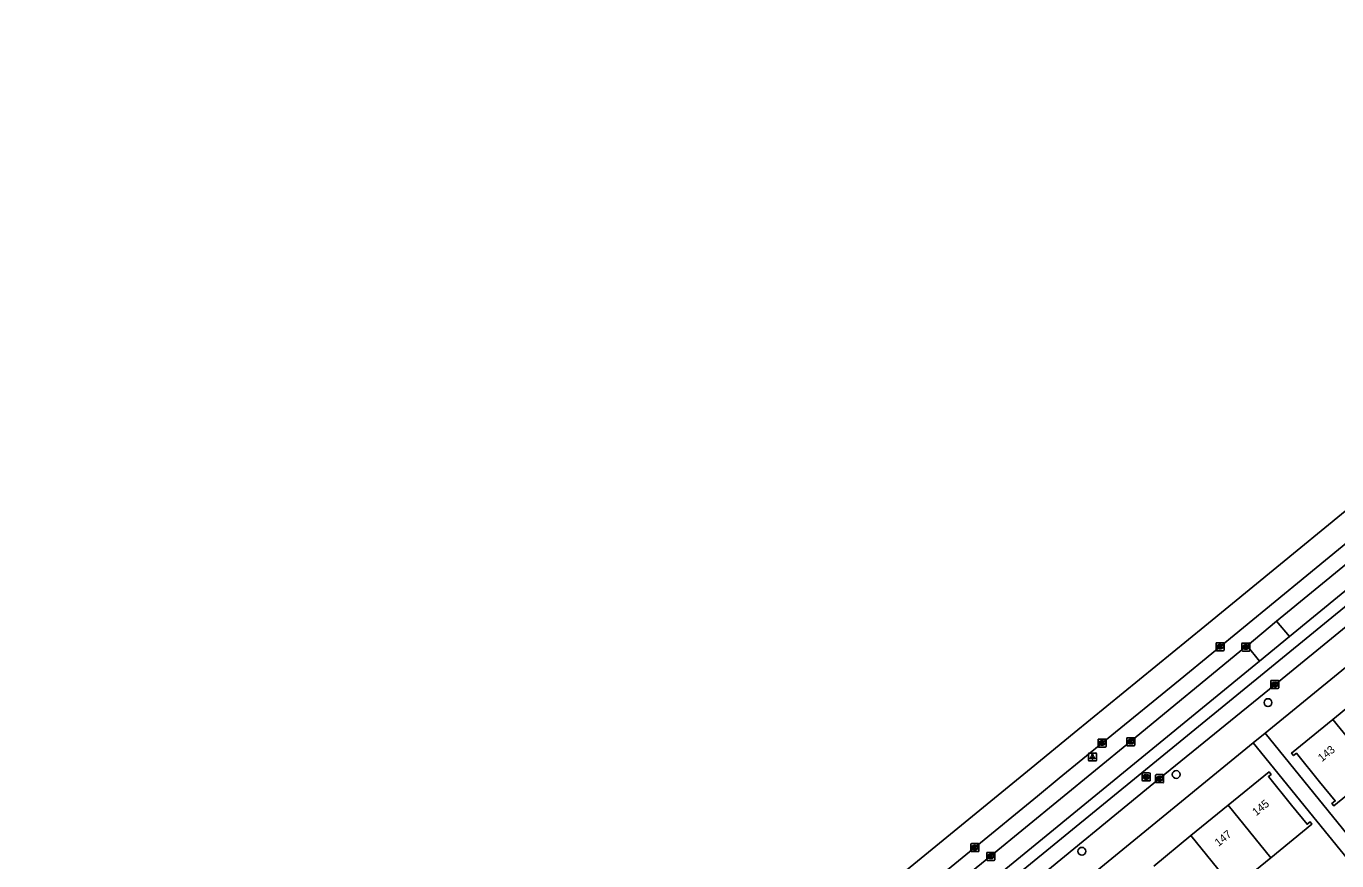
# Model space of a CAD drawing. Extents: x 162532 to 163264, y 381233 to 382042.
# Drawn here: x 162536.5 to 162700.3, y 381924.3 to 382028.5 of the extents above; entities that cross this region are included whole.
import ezdxf

# ---------------------------------------------------------------- set-up
doc = ezdxf.new("R2010")
doc.units = 0
for name, color, linetype in [('IMGEO_Boom', 7, 'Continuous'), ('IMGEO_Kolk', 7, 'Continuous'), ('IMGEO_Lichtpunt', 7, 'Continuous'), ('IMGEO_Pand', 7, 'Continuous'), ('IMGEO_Pand_nummerreeks', 7, 'Continuous'), ('IMGEO_Rijbaan_lokaal_gesloten', 7, 'Continuous'), ('IMGEO_Rijbaan_lokaal_open', 7, 'Continuous'), ('IMGEO_Rijbaan_regionaal_gesloten', 7, 'Continuous'), ('IMGEO_Rioolput', 7, 'Continuous'), ('IMGEO_Voetpad_open', 7, 'Continuous')]:
    doc.layers.add(name, color=color, linetype=linetype)

msp = doc.modelspace()

# ---------------------------------------------------------------- linework, layer by layer
at = {"layer": 'IMGEO_Boom'}
for centre in [(162691.72, 381944.05), (162680.25, 381935.07), (162668.46, 381925.48)]:
    msp.add_circle(centre, 0.489, dxfattribs=at)
at = {"layer": 'IMGEO_Kolk'}
for p, q in [((162685.23, 381950.6), (162685.23, 381951.45)), ((162685.3, 381951.53), (162686.16, 381951.53)), ((162685.72, 381951.31), (162685.74, 381951.31)), ((162685.74, 381950.75), (162685.72, 381950.75)), ((162686.23, 381951.45), (162686.23, 381950.6)), ((162688.46, 381950.57), (162688.46, 381951.42)), ((162688.53, 381951.49), (162689.38, 381951.49)), ((162688.94, 381951.27), (162688.97, 381951.27)), ((162688.97, 381950.71), (162688.94, 381950.71)), ((162689.46, 381951.42), (162689.46, 381950.57)), ((162686.16, 381950.53), (162685.3, 381950.53)), ((162689.38, 381950.49), (162688.53, 381950.49)), ((162692.07, 381945.89), (162692.07, 381946.74)), ((162692.15, 381946.81), (162693, 381946.81)), ((162693, 381945.81), (162692.15, 381945.81)), ((162692.56, 381946.59), (162692.59, 381946.59)), ((162692.58, 381946.03), (162692.56, 381946.03)), ((162693.07, 381946.74), (162693.07, 381945.89)), ((162670.48, 381938.57), (162670.48, 381939.42)), ((162670.56, 381939.5), (162671.41, 381939.5)), ((162670.97, 381939.28), (162671, 381939.28)), ((162671.48, 381939.42), (162671.48, 381938.57)), ((162674.08, 381938.73), (162674.08, 381939.59)), ((162674.15, 381939.66), (162675, 381939.66)), ((162674.56, 381939.44), (162674.59, 381939.44)), ((162675.08, 381939.59), (162675.08, 381938.73)), ((162671.41, 381938.5), (162670.56, 381938.5)), ((162670.99, 381938.72), (162670.97, 381938.72)), ((162675, 381938.66), (162674.15, 381938.66)), ((162674.59, 381938.88), (162674.56, 381938.88)), ((162677.67, 381934.12), (162677.67, 381934.97)), ((162677.74, 381935.05), (162678.6, 381935.05)), ((162678.18, 381934.27), (162678.15, 381934.27)), ((162678.16, 381934.83), (162678.18, 381934.83)), ((162678.67, 381934.97), (162678.67, 381934.12)), ((162678.6, 381934.05), (162677.74, 381934.05)), ((162654.58, 381925.52), (162654.58, 381926.38)), ((162654.66, 381926.45), (162655.51, 381926.45)), ((162655.07, 381926.23), (162655.1, 381926.23)), ((162655.58, 381926.38), (162655.58, 381925.52)), ((162655.51, 381925.45), (162654.66, 381925.45)), ((162655.09, 381925.67), (162655.07, 381925.67)), ((162656.57, 381924.41), (162656.57, 381925.26)), ((162656.64, 381925.34), (162657.49, 381925.34)), ((162657.05, 381925.12), (162657.08, 381925.12)), ((162657.08, 381924.56), (162657.05, 381924.56)), ((162657.57, 381925.26), (162657.57, 381924.41)), ((162657.49, 381924.34), (162656.64, 381924.34))]:
    msp.add_line(p, q, dxfattribs=at)
for points in [[(162685.23, 381950.6), (162685.23, 381951.45)], [(162685.3, 381951.53), (162686.16, 381951.53)], [(162685.55, 381951.23), (162685.67, 381951.23), (162685.67, 381951.08), (162685.8, 381951.23), (162685.97, 381951.23), (162685.82, 381951.08), (162685.97, 381950.83), (162685.82, 381950.83), (162685.74, 381950.99), (162685.67, 381950.93), (162685.67, 381950.83), (162685.55, 381950.83), (162685.55, 381951.23)], [(162686.23, 381951.45), (162686.23, 381950.6)], [(162688.46, 381950.57), (162688.46, 381951.42)], [(162688.53, 381951.49), (162689.38, 381951.49)], [(162688.78, 381951.19), (162688.9, 381951.19), (162688.9, 381951.04), (162689.03, 381951.19), (162689.19, 381951.19), (162689.05, 381951.04), (162689.2, 381950.79), (162689.05, 381950.79), (162688.96, 381950.96), (162688.9, 381950.89), (162688.9, 381950.79), (162688.78, 381950.79), (162688.78, 381951.19)], [(162689.46, 381951.42), (162689.46, 381950.57)], [(162686.16, 381950.53), (162685.3, 381950.53)], [(162689.38, 381950.49), (162688.53, 381950.49)], [(162692.07, 381945.89), (162692.07, 381946.74)], [(162692.15, 381946.81), (162693, 381946.81)], [(162693, 381945.81), (162692.15, 381945.81)], [(162692.39, 381946.51), (162692.52, 381946.51), (162692.52, 381946.36), (162692.65, 381946.51), (162692.81, 381946.51), (162692.67, 381946.36), (162692.82, 381946.11), (162692.67, 381946.11), (162692.58, 381946.28), (162692.52, 381946.21), (162692.52, 381946.11), (162692.39, 381946.11), (162692.39, 381946.51)], [(162693.07, 381946.74), (162693.07, 381945.89)], [(162670.48, 381938.57), (162670.48, 381939.42)], [(162670.56, 381939.5), (162671.41, 381939.5)], [(162670.8, 381939.2), (162670.93, 381939.2), (162670.93, 381939.04), (162671.06, 381939.2), (162671.22, 381939.2), (162671.07, 381939.05), (162671.23, 381938.8), (162671.07, 381938.8), (162670.99, 381938.96), (162670.93, 381938.89), (162670.93, 381938.8), (162670.8, 381938.8), (162670.8, 381939.2)], [(162671.48, 381939.42), (162671.48, 381938.57)], [(162674.08, 381938.73), (162674.08, 381939.59)], [(162674.15, 381939.66), (162675, 381939.66)], [(162674.4, 381939.36), (162674.52, 381939.36), (162674.52, 381939.21), (162674.65, 381939.36), (162674.81, 381939.36), (162674.67, 381939.21), (162674.82, 381938.96), (162674.67, 381938.96), (162674.58, 381939.12), (162674.52, 381939.06), (162674.52, 381938.96), (162674.4, 381938.96), (162674.4, 381939.36)], [(162675.08, 381939.59), (162675.08, 381938.73)], [(162671.41, 381938.5), (162670.56, 381938.5)], [(162675, 381938.66), (162674.15, 381938.66)], [(162677.67, 381934.12), (162677.67, 381934.97)], [(162677.74, 381935.05), (162678.6, 381935.05)], [(162677.99, 381934.75), (162678.11, 381934.75), (162678.11, 381934.6), (162678.24, 381934.75), (162678.41, 381934.75), (162678.26, 381934.6), (162678.41, 381934.35), (162678.26, 381934.35), (162678.18, 381934.51), (162678.11, 381934.45), (162678.11, 381934.35), (162677.99, 381934.35), (162677.99, 381934.75)], [(162678.67, 381934.97), (162678.67, 381934.12)], [(162678.6, 381934.05), (162677.74, 381934.05)], [(162654.58, 381925.52), (162654.58, 381926.38)], [(162654.66, 381926.45), (162655.51, 381926.45)], [(162654.9, 381926.15), (162655.03, 381926.15), (162655.03, 381926), (162655.16, 381926.15), (162655.32, 381926.15), (162655.17, 381926), (162655.33, 381925.75), (162655.17, 381925.75), (162655.09, 381925.91), (162655.03, 381925.85), (162655.03, 381925.75), (162654.9, 381925.75), (162654.9, 381926.15)], [(162655.58, 381926.38), (162655.58, 381925.52)], [(162655.51, 381925.45), (162654.66, 381925.45)], [(162656.57, 381924.41), (162656.57, 381925.26)], [(162656.64, 381925.34), (162657.49, 381925.34)], [(162656.89, 381925.04), (162657.01, 381925.04), (162657.01, 381924.89), (162657.14, 381925.04), (162657.3, 381925.04), (162657.16, 381924.89), (162657.31, 381924.64), (162657.16, 381924.64), (162657.07, 381924.8), (162657.01, 381924.73), (162657.01, 381924.64), (162656.89, 381924.64), (162656.89, 381925.04)], [(162657.57, 381925.26), (162657.57, 381924.41)], [(162657.49, 381924.34), (162656.64, 381924.34)]]:
    msp.add_lwpolyline(points, dxfattribs=at)
for centre, start, end in [((162685.31, 381951.45), 91.552, 178.448), ((162685.31, 381951.45), 91.552, 178.448), ((162686.15, 381951.45), 1.552, 88.448), ((162686.15, 381951.45), 1.552, 88.448), ((162688.53, 381951.42), 91.552, 178.448), ((162688.53, 381951.42), 91.552, 178.448), ((162689.38, 381951.42), 1.552, 88.448), ((162689.38, 381951.42), 1.552, 88.448), ((162685.31, 381950.6), 181.552, 268.448), ((162685.31, 381950.6), 181.552, 268.448), ((162686.15, 381950.6), 271.552, 358.448), ((162686.15, 381950.6), 271.552, 358.448), ((162688.53, 381950.57), 181.552, 268.448), ((162688.53, 381950.57), 181.552, 268.448), ((162689.38, 381950.57), 271.552, 358.448), ((162689.38, 381950.57), 271.552, 358.448), ((162692.15, 381946.74), 91.552, 178.448), ((162692.15, 381946.74), 91.552, 178.448), ((162692.15, 381945.89), 181.552, 268.448), ((162692.15, 381945.89), 181.552, 268.448), ((162693, 381946.74), 1.552, 88.448), ((162693, 381946.74), 1.552, 88.448), ((162693, 381945.89), 271.552, 358.448), ((162693, 381945.89), 271.552, 358.448), ((162670.56, 381939.42), 91.552, 178.448), ((162670.56, 381939.42), 91.552, 178.448), ((162671.41, 381939.42), 1.552, 88.448), ((162671.41, 381939.42), 1.552, 88.448), ((162674.15, 381939.58), 91.552, 178.448), ((162674.15, 381939.58), 91.552, 178.448), ((162675, 381939.58), 1.552, 88.448), ((162675, 381939.58), 1.552, 88.448), ((162670.56, 381938.57), 181.552, 268.448), ((162670.56, 381938.57), 181.552, 268.448), ((162671.41, 381938.57), 271.552, 358.448), ((162671.41, 381938.57), 271.552, 358.448), ((162674.15, 381938.74), 181.552, 268.448), ((162674.15, 381938.74), 181.552, 268.448), ((162675, 381938.74), 271.552, 358.448), ((162675, 381938.74), 271.552, 358.448), ((162677.74, 381934.97), 91.552, 178.448), ((162677.74, 381934.97), 91.552, 178.448), ((162678.59, 381934.97), 1.552, 88.448), ((162678.59, 381934.97), 1.552, 88.448), ((162677.74, 381934.12), 181.552, 268.448), ((162677.74, 381934.12), 181.552, 268.448), ((162678.59, 381934.12), 271.552, 358.448), ((162678.59, 381934.12), 271.552, 358.448), ((162654.66, 381926.37), 91.552, 178.448), ((162654.66, 381926.37), 91.552, 178.448), ((162655.51, 381926.37), 1.552, 88.448), ((162655.51, 381926.37), 1.552, 88.448), ((162654.66, 381925.52), 181.552, 268.448), ((162654.66, 381925.52), 181.552, 268.448), ((162655.51, 381925.52), 271.552, 358.448), ((162655.51, 381925.52), 271.552, 358.448), ((162656.64, 381925.26), 91.552, 178.448), ((162656.64, 381925.26), 91.552, 178.448), ((162656.64, 381924.41), 181.552, 268.448), ((162656.64, 381924.41), 181.552, 268.448), ((162657.49, 381925.26), 1.552, 88.448), ((162657.49, 381925.26), 1.552, 88.448), ((162657.49, 381924.41), 271.552, 358.448), ((162657.49, 381924.41), 271.552, 358.448)]:
    msp.add_arc(centre, 0.0765, start, end, dxfattribs=at)
for centre, major_axis, ratio, start_param, end_param in [((162685.72, 381951.03), (-0.387, 0.002), 0.722429, 4.712389, 7.853982), ((162685.74, 381951.03), (-0.39, 0.002), 0.717154, 1.570796, 4.712389), ((162688.94, 381950.99), (-0.387, 0.002), 0.722429, 4.712389, 7.853982), ((162688.97, 381950.99), (-0.39, 0.002), 0.717154, 1.570796, 4.712389), ((162692.56, 381946.31), (-0.387, 0.002), 0.722429, 4.712389, 7.853982), ((162692.58, 381946.31), (-0.39, 0.002), 0.717154, 1.570796, 4.712389), ((162670.97, 381939), (-0.387, 0.002), 0.722429, 4.712389, 7.853982), ((162670.99, 381939), (-0.39, 0.002), 0.717154, 1.570796, 4.712389), ((162674.56, 381939.16), (-0.387, 0.002), 0.722429, 4.712389, 7.853982), ((162674.59, 381939.16), (-0.39, 0.002), 0.717154, 1.570796, 4.712389), ((162678.16, 381934.55), (-0.387, 0.002), 0.722429, 4.712389, 7.853982), ((162678.18, 381934.55), (-0.39, 0.002), 0.717154, 1.570796, 4.712389), ((162655.07, 381925.95), (-0.387, 0.002), 0.722429, 4.712389, 7.853982), ((162655.09, 381925.95), (-0.39, 0.002), 0.717154, 1.570796, 4.712389), ((162657.05, 381924.84), (-0.387, 0.002), 0.722429, 4.712389, 7.853982), ((162657.08, 381924.84), (-0.39, 0.002), 0.717154, 1.570796, 4.712389)]:
    msp.add_ellipse(centre, major_axis=major_axis, ratio=ratio, start_param=start_param, end_param=end_param, dxfattribs=at)
at = {"layer": 'IMGEO_Lichtpunt'}
for p, q in [((162669.28, 381937.66), (162669.28, 381936.85)), ((162669.28, 381937.66), (162669.28, 381936.85)), ((162670.18, 381937.75), (162669.38, 381937.75)), ((162670.18, 381937.75), (162669.38, 381937.75)), ((162670.28, 381936.85), (162670.28, 381937.66)), ((162670.28, 381936.85), (162670.28, 381937.66)), ((162669.38, 381936.76), (162670.18, 381936.76)), ((162669.38, 381936.76), (162670.18, 381936.76))]:
    msp.add_line(p, q, dxfattribs=at)
for points in [[(162669.66, 381937.32), (162669.7, 381937.29), (162669.51, 381937.03), (162669.47, 381937.06), (162669.66, 381937.32)], [(162669.76, 381937.27), (162669.81, 381937.27), (162669.81, 381936.95), (162669.76, 381936.95), (162669.76, 381937.27)], [(162669.87, 381937.29), (162669.91, 381937.32), (162670.09, 381937.06), (162670.06, 381937.03), (162669.87, 381937.29)]]:
    msp.add_lwpolyline(points, dxfattribs=at)
msp.add_circle((162669.78, 381937.46), 0.0994, dxfattribs=at)
for centre, start, end in [((162669.38, 381937.66), 90, 180), ((162669.38, 381937.66), 90, 180), ((162670.18, 381937.66), 0, 90), ((162670.18, 381937.66), 0, 90), ((162669.38, 381936.85), 180, 270), ((162669.38, 381936.85), 180, 270), ((162670.18, 381936.85), 270, 0), ((162670.18, 381936.85), 270, 360)]:
    msp.add_arc(centre, 0.0946, start, end, dxfattribs=at)
at = {"layer": 'IMGEO_Pand'}
for points in [[(162699.82, 381941.94), (162704.47, 381945.73)], [(162705.14, 381935.41), (162699.94, 381931.17), (162699.72, 381931.45), (162700.12, 381931.77), (162698.18, 381934.16), (162695.27, 381937.73), (162694.92, 381937.44), (162694.67, 381937.74), (162699.82, 381941.94)], [(162699.82, 381941.94), (162705.14, 381935.41)], [(162686.74, 381931.22), (162691.85, 381935.39), (162692.11, 381935.07), (162691.77, 381934.8), (162694.68, 381931.24), (162696.61, 381928.86), (162696.98, 381929.16), (162697.21, 381928.87), (162692.07, 381924.68)], [(162682.09, 381927.43), (162686.74, 381931.22)], [(162686.74, 381931.22), (162692.07, 381924.68)], [(162677.44, 381923.64), (162682.09, 381927.43)], [(162687.42, 381920.89), (162682.09, 381927.43)], [(162692.07, 381924.68), (162687.42, 381920.89)]]:
    msp.add_lwpolyline(points, dxfattribs=at)
at = {"layer": 'IMGEO_Rijbaan_lokaal_gesloten'}
for points in [[(162694.41, 381952.3), (162718.17, 381971.74), (162730.76, 381982.04), (162739.98, 381989.55)], [(162734.88, 381983.41), (162719.33, 381970.72), (162660.67, 381922.78), (162621.16, 381890.44), (162606.54, 381878.62)], [(162690.66, 381949.23), (162620.31, 381891.69), (162605.63, 381879.75)]]:
    msp.add_lwpolyline(points, dxfattribs=at)
at = {"layer": 'IMGEO_Rijbaan_lokaal_open'}
for points in [[(162692.8, 381954.24), (162706.36, 381965.32), (162723.06, 381979.02), (162732.21, 381986.5)], [(162689.11, 381951.16), (162692.8, 381954.24)], [(162692.8, 381954.24), (162694.41, 381952.3)], [(162694.41, 381952.3), (162690.66, 381949.23)], [(162603.99, 381881.71), (162607.58, 381884.56), (162623.56, 381897.65), (162657.02, 381924.88), (162674.52, 381939.19), (162688.9, 381951.03), (162689.11, 381951.16)], [(162689.11, 381951.16), (162690.66, 381949.23)]]:
    msp.add_lwpolyline(points, dxfattribs=at)
at = {"layer": 'IMGEO_Rijbaan_regionaal_gesloten'}
for points in [[(162536.51, 381827.18), (162540.16, 381830.79), (162552.38, 381842.71), (162567, 381856.38), (162572.1, 381861.05), (162587.25, 381874.27), (162599.48, 381884.47), (162624.29, 381904.91), (162662.12, 381935.84), (162667.51, 381940.27), (162683.82, 381953.59), (162710.36, 381975.32), (162716.01, 381979.97), (162720.8, 381983.88), (162725.3, 381987.52), (162732.27, 381992.77), (162738.68, 381997.54), (162745.06, 382002.25), (162751.54, 382007.05), (162758.02, 382011.86), (162764.4, 382016.6), (162770.79, 382021.33), (162777.28, 382026.14), (162780.54, 382028.53)], [(162562.15, 381847.42), (162563.05, 381848.27), (162568.79, 381853.73), (162570.54, 381855.35), (162576.65, 381860.8), (162581.63, 381865.19), (162587.81, 381870.58), (162593.66, 381875.67), (162600.28, 381881.21), (162616.9, 381894.77), (162628.27, 381903.98), (162646.84, 381919.2), (162662.91, 381932.36), (162665.64, 381934.61), (162671.53, 381939.45), (162680.74, 381946.93), (162688.64, 381953.42), (162696.58, 381959.93), (162705.64, 381967.39), (162712.5, 381972.94), (162718.87, 381978.13), (162722.18, 381980.8), (162726.01, 381983.56)]]:
    msp.add_lwpolyline(points, dxfattribs=at)
at = {"layer": 'IMGEO_Rioolput'}
for p, q in [((162676, 381934.35), (162676, 381935.2)), ((162676.08, 381935.27), (162676.93, 381935.27)), ((162676.93, 381934.27), (162676.08, 381934.27)), ((162676.49, 381935.05), (162676.51, 381935.05)), ((162676.51, 381934.49), (162676.49, 381934.49)), ((162677, 381935.2), (162677, 381934.35))]:
    msp.add_line(p, q, dxfattribs=at)
for points in [[(162676, 381934.35), (162676, 381935.2)], [(162676.08, 381935.27), (162676.93, 381935.27)], [(162676.93, 381934.27), (162676.08, 381934.27)], [(162676.59, 381934.97), (162676.34, 381934.97), (162676.34, 381934.57)], [(162676.34, 381934.57), (162676.46, 381934.57), (162676.46, 381934.74), (162676.47, 381934.74)], [(162676.52, 381934.89), (162676.46, 381934.89), (162676.46, 381934.81)], [(162676.46, 381934.81), (162676.51, 381934.81)], [(162676.52, 381934.71), (162676.59, 381934.57), (162676.73, 381934.57), (162676.67, 381934.7)], [(162677, 381935.2), (162677, 381934.35)]]:
    msp.add_lwpolyline(points, dxfattribs=at)
for centre, radius, start, end in [((162676.08, 381935.2), 0.0765, 91.552, 178.448), ((162676.08, 381935.2), 0.0765, 91.552, 178.448), ((162676.08, 381934.35), 0.0765, 181.552, 268.448), ((162676.08, 381934.35), 0.0765, 181.552, 268.448), ((162676.47, 381934.68), 0.0533, 26.0293, 88.6989), ((162676.5, 381935), 0.19, 274.7715, 282.9687), ((162676.52, 381934.8), 0.0964, 77.0061, 93.1865), ((162676.54, 381934.85), 0.0378, 276.6634, 79.6772), ((162676.59, 381934.86), 0.109, 350.3612, 89.416), ((162676.59, 381934.86), 0.112, 277.5842, 350.9817), ((162676.57, 381934.65), 0.108, 29.5134, 73.7905), ((162676.93, 381935.2), 0.0765, 1.552, 88.448), ((162676.93, 381935.2), 0.0765, 1.552, 88.448), ((162676.93, 381934.35), 0.0765, 271.552, 358.448), ((162676.93, 381934.35), 0.0765, 271.552, 358.448)]:
    msp.add_arc(centre, radius, start, end, dxfattribs=at)
for centre, major_axis, ratio, start_param, end_param in [((162676.49, 381934.77), (-0.387, 0.002), 0.722429, 4.712389, 7.853982), ((162676.51, 381934.77), (-0.39, 0.002), 0.717154, 1.570796, 4.712389)]:
    msp.add_ellipse(centre, major_axis=major_axis, ratio=ratio, start_param=start_param, end_param=end_param, dxfattribs=at)
at = {"layer": 'IMGEO_Voetpad_open'}
for points in [[(162733.63, 381980.89), (162733.54, 381980.14), (162733.17, 381979.5), (162726.8, 381974.27), (162710.87, 381961.23), (162692.56, 381946.28), (162678.17, 381934.55), (162660.69, 381920.23), (162645.53, 381907.81), (162628.02, 381893.55), (162627.05, 381892.75)], [(162721.51, 381964.85), (162691.38, 381940.25)], [(162689.86, 381939.01), (162691.38, 381940.25)], [(162691.38, 381940.25), (162707.12, 381920.81), (162709.1, 381922.41), (162729.42, 381938.8)], [(162689.86, 381939.01), (162659.56, 381914.27)], [(162697.24, 381912.81), (162705.64, 381919.61), (162697.84, 381929.24), (162689.86, 381939.01)]]:
    msp.add_lwpolyline(points, dxfattribs=at)

# ---------------------------------------------------------------- texts
at = {"layer": 'IMGEO_Pand_nummerreeks'}
for s, rotation, p in [('143', 39.1755, (162698.46, 381936.6)), ('145', 39.1778, (162690.25, 381929.84)), ('147', 39.1778, (162685.55, 381926.02))]:
    msp.add_text(s, height=1, rotation=rotation, dxfattribs=at).set_placement(p)

doc.saveas('drawing.dxf')
